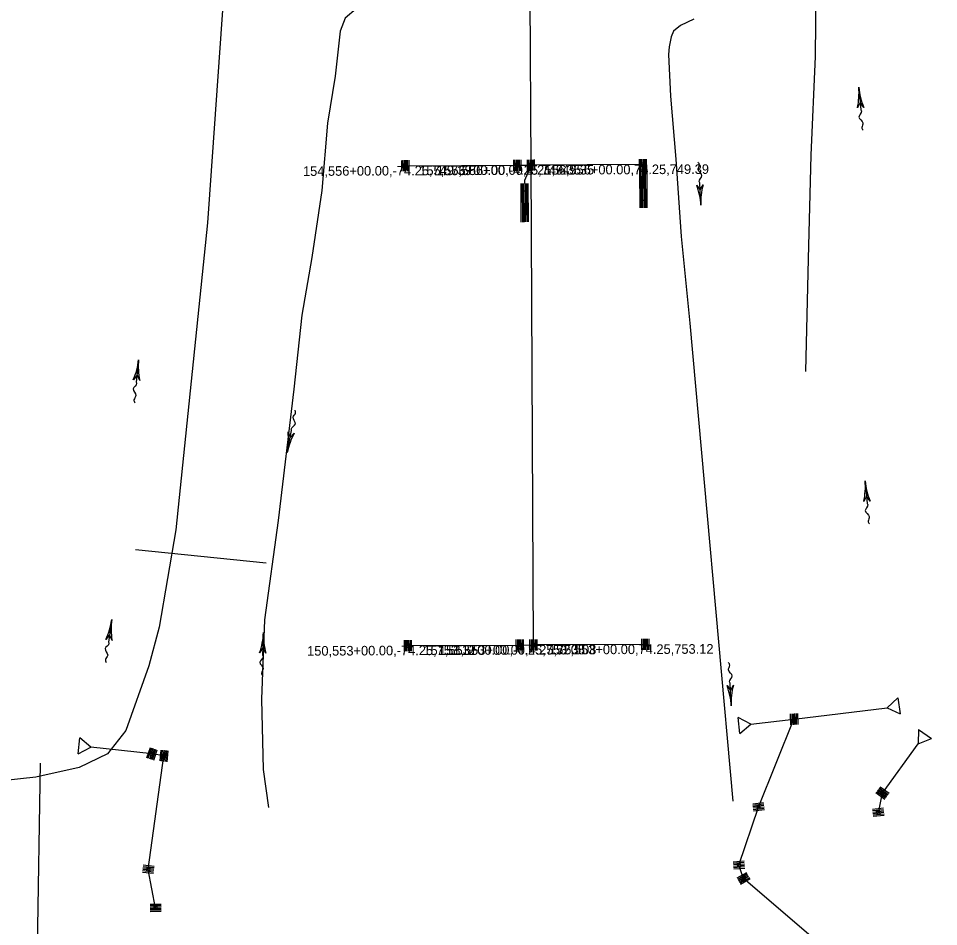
# Model space of a CAD drawing. Extents: x 593481 to 595602, y 151646 to 157396.
# Drawn here: x 594038 to 594613, y 154399 to 154967 of the extents above; entities that cross this region are included whole.
import ezdxf

# ---------------------------------------------------------------- set-up
doc = ezdxf.new("R2010")
doc.units = 0
for name, color, linetype in [('P_ALI_50_Equation', 7, 'Continuous'), ('P_DRN_Flow', 7, 'Continuous'), ('P_DRN_Inlet', 7, 'Continuous'), ('P_DRN_Pipes', 7, 'Continuous'), ('P_DRN_SS', 7, 'Continuous'), ('P_DRN_SS_UG', 7, 'Continuous')]:
    doc.layers.add(name, color=color, linetype=linetype)

msp = doc.modelspace()

# ---------------------------------------------------------------- linework, layer by layer
at = {"layer": 'P_DRN_Flow'}
for p, q in [((594563.04, 154923.95), (594564.3, 154909.88)), ((594464.36, 154850.16), (594463.66, 154864.27)), ((594112.88, 154753.62), (594111.44, 154739.56)), ((594205.82, 154695.54), (594208.51, 154709.41)), ((594567, 154677.84), (594568.26, 154663.77)), ((594096.09, 154591.1), (594094.11, 154577.11)), ((594190.93, 154582.97), (594190.43, 154568.85)), ((594483.33, 154537.28), (594482.62, 154551.39))]:
    msp.add_line(p, q, dxfattribs=at)
for points in [[(594566.18, 154911.38), (594563.9, 154914.39), (594562.19, 154911.02)], [(594461.72, 154862.84), (594463.88, 154859.75), (594465.72, 154863.05)], [(594113.56, 154740.68), (594111.9, 154744.07), (594109.59, 154741.09)], [(594206.29, 154708.49), (594207.64, 154704.96), (594210.22, 154707.73)], [(594570.14, 154665.27), (594567.86, 154668.28), (594566.15, 154664.91)], [(594096.28, 154578.15), (594094.75, 154581.6), (594092.32, 154578.71)], [(594192.48, 154570.11), (594190.59, 154573.38), (594188.48, 154570.25)], [(594480.69, 154549.96), (594482.84, 154546.86), (594484.68, 154550.16)]]:
    msp.add_lwpolyline(points, dxfattribs=at)
for centre, start, end in [((594521.25, 154920.21), 347.35833, 5.12065), ((594604.83, 154927.7), 185.12065, 202.88297), ((594422.46, 154848.06), 2.86546, 20.62778), ((594506.27, 154852.26), 165.10314, 182.86546), ((594071.14, 154757.91), 336.36566, 354.12798), ((594154.62, 154749.32), 174.12798, 191.8903), ((594164.63, 154703.54), 349.00666, 6.76898), ((594247, 154687.54), 151.24434, 169.00666), ((594525.21, 154674.09), 347.35833, 5.12065), ((594608.79, 154681.58), 185.12065, 202.88297), ((594054.55, 154597), 334.15876, 351.92108), ((594137.64, 154585.21), 171.92108, 189.6834), ((594149, 154584.46), 340.19919, 357.96151), ((594232.86, 154581.48), 177.96151, 195.72383), ((594441.42, 154535.18), 2.86546, 20.62778), ((594525.23, 154539.37), 165.10314, 182.86546)]:
    msp.add_arc(centre, 41.96, start, end, dxfattribs=at)
for points in [[(594564.3, 154909.88), (594564.68, 154909.13), (594563.13, 154905.36), (594565.67, 154901.65), (594564.98, 154898.75), (594565.76, 154897.09)], [(594463.66, 154864.27), (594463.3, 154865.04), (594465, 154868.74), (594462.61, 154872.55), (594463.41, 154875.42), (594462.7, 154877.11)], [(594111.44, 154739.56), (594111.67, 154738.75), (594109.43, 154735.35), (594111.21, 154731.22), (594109.98, 154728.51), (594110.43, 154726.72)], [(594208.51, 154709.41), (594208.35, 154710.24), (594210.89, 154713.43), (594209.48, 154717.7), (594210.95, 154720.29), (594210.66, 154722.11)], [(594568.26, 154663.77), (594568.64, 154663.01), (594567.09, 154659.25), (594569.63, 154655.54), (594568.94, 154652.64), (594569.72, 154650.97)], [(594094.11, 154577.11), (594094.31, 154576.29), (594091.94, 154572.98), (594093.56, 154568.79), (594092.23, 154566.12), (594092.61, 154564.33)], [(594190.43, 154568.85), (594190.71, 154568.05), (594188.7, 154564.51), (594190.76, 154560.51), (594189.72, 154557.72), (594190.28, 154555.97)], [(594482.62, 154551.39), (594482.27, 154552.15), (594483.97, 154555.86), (594481.58, 154559.66), (594482.38, 154562.53), (594481.66, 154564.23)]]:
    msp.add_spline(points, degree=3, dxfattribs=at)
at = {"layer": 'P_DRN_Inlet'}
for p, q in [((594277.49, 154871.4), (594277.45, 154878.27)), ((594278.39, 154871.4), (594278.35, 154878.28)), ((594279.29, 154871.41), (594279.25, 154878.28)), ((594280.19, 154871.41), (594280.15, 154878.29)), ((594281.09, 154871.42), (594281.05, 154878.29)), ((594281.99, 154871.42), (594281.95, 154878.3)), ((594347.49, 154871.76), (594347.45, 154878.63)), ((594348.39, 154871.76), (594348.35, 154878.64)), ((594349.29, 154871.77), (594349.25, 154878.64)), ((594350.19, 154871.77), (594350.15, 154878.65)), ((594351.09, 154871.78), (594351.05, 154878.65)), ((594351.99, 154871.78), (594351.95, 154878.66)), ((594355.99, 154871.8), (594355.95, 154878.68)), ((594356.89, 154871.81), (594356.85, 154878.68)), ((594357.79, 154871.81), (594357.75, 154878.69)), ((594358.69, 154871.81), (594358.65, 154878.69)), ((594359.59, 154871.82), (594359.55, 154878.69)), ((594360.49, 154871.82), (594360.45, 154878.7)), ((594425.99, 154872.16), (594425.95, 154879.04)), ((594426.89, 154872.16), (594426.85, 154879.04)), ((594427.79, 154872.17), (594427.75, 154879.04)), ((594428.69, 154872.17), (594428.65, 154879.05)), ((594429.59, 154872.18), (594429.55, 154879.05)), ((594430.49, 154872.18), (594430.45, 154879.06)), ((594425.99, 154872.6), (594426.11, 154848.6)), ((594426.89, 154872.6), (594427.01, 154848.6)), ((594427.79, 154872.61), (594427.91, 154848.61)), ((594428.69, 154872.61), (594428.81, 154848.61)), ((594429.59, 154872.62), (594429.71, 154848.62)), ((594430.49, 154872.62), (594430.61, 154848.62)), ((594351.77, 154863.71), (594351.89, 154839.71)), ((594352.67, 154863.72), (594352.79, 154839.72)), ((594353.57, 154863.72), (594353.69, 154839.72)), ((594354.47, 154863.73), (594354.59, 154839.73)), ((594355.37, 154863.73), (594355.49, 154839.73)), ((594356.27, 154863.74), (594356.39, 154839.74)), ((594279.03, 154571.4), (594278.99, 154578.28)), ((594279.93, 154571.41), (594279.89, 154578.28)), ((594280.83, 154571.41), (594280.79, 154578.29)), ((594281.73, 154571.42), (594281.69, 154578.29)), ((594282.63, 154571.42), (594282.59, 154578.3)), ((594283.53, 154571.43), (594283.49, 154578.3)), ((594349.03, 154571.76), (594348.99, 154578.64)), ((594349.93, 154571.77), (594349.89, 154578.64)), ((594350.83, 154571.77), (594350.79, 154578.65)), ((594351.73, 154571.78), (594351.69, 154578.65)), ((594352.63, 154571.78), (594352.59, 154578.65)), ((594353.53, 154571.78), (594353.49, 154578.66)), ((594357.53, 154571.8), (594357.49, 154578.68)), ((594358.43, 154571.81), (594358.39, 154578.68)), ((594359.33, 154571.81), (594359.29, 154578.69)), ((594360.23, 154571.82), (594360.19, 154578.69)), ((594361.13, 154571.82), (594361.09, 154578.7)), ((594362.03, 154571.83), (594361.99, 154578.7)), ((594427.53, 154572.16), (594427.49, 154579.04)), ((594428.43, 154572.17), (594428.39, 154579.04)), ((594429.33, 154572.17), (594429.29, 154579.05)), ((594430.23, 154572.18), (594430.19, 154579.05)), ((594431.13, 154572.18), (594431.09, 154579.06)), ((594432.03, 154572.19), (594431.99, 154579.06)), ((594520.24, 154532.25), (594520.38, 154525.38)), ((594521.14, 154532.27), (594521.28, 154525.4)), ((594522.04, 154532.29), (594522.18, 154525.42)), ((594522.94, 154532.31), (594523.08, 154525.44)), ((594523.84, 154532.33), (594523.98, 154525.45)), ((594524.74, 154532.35), (594524.88, 154525.47)), ((594118.1, 154504.73), (594120.32, 154511.24)), ((594118.95, 154504.44), (594121.17, 154510.94)), ((594119.8, 154504.15), (594122.03, 154510.65)), ((594120.65, 154503.86), (594122.88, 154510.36)), ((594121.5, 154503.57), (594123.73, 154510.07)), ((594122.35, 154503.27), (594124.58, 154509.78)), ((594126.76, 154509.59), (594126.05, 154502.75)), ((594127.65, 154509.49), (594126.95, 154502.66)), ((594128.55, 154509.4), (594127.84, 154502.56)), ((594129.44, 154509.31), (594128.74, 154502.47)), ((594130.34, 154509.22), (594129.63, 154502.38)), ((594131.23, 154509.12), (594130.53, 154502.29)), ((594579.3, 154478.71), (594573.76, 154482.79)), ((594579.83, 154479.44), (594574.3, 154483.51)), ((594580.37, 154480.16), (594574.83, 154484.24)), ((594580.9, 154480.89), (594575.36, 154484.96)), ((594581.43, 154481.61), (594575.89, 154485.69)), ((594581.97, 154482.34), (594576.43, 154486.41)), ((594503.56, 154476.57), (594496.73, 154475.8)), ((594503.66, 154475.68), (594496.83, 154474.91)), ((594503.76, 154474.79), (594496.93, 154474.02)), ((594503.86, 154473.89), (594497.03, 154473.12)), ((594503.96, 154473), (594497.13, 154472.23)), ((594504.06, 154472.1), (594497.23, 154471.33)), ((594578.47, 154473.14), (594571.64, 154472.4)), ((594578.57, 154472.24), (594571.73, 154471.5)), ((594578.67, 154471.35), (594571.83, 154470.61)), ((594578.76, 154470.45), (594571.93, 154469.71)), ((594578.86, 154469.56), (594572.02, 154468.82)), ((594578.96, 154468.66), (594572.12, 154467.92)), ((594122.51, 154435.95), (594115.67, 154436.64)), ((594122.6, 154436.85), (594115.76, 154437.53)), ((594491.43, 154440.07), (594484.57, 154439.54)), ((594491.5, 154439.17), (594484.64, 154438.64)), ((594491.56, 154438.27), (594484.71, 154437.74)), ((594491.63, 154437.38), (594484.78, 154436.85)), ((594491.7, 154436.48), (594484.85, 154435.95)), ((594122.15, 154432.37), (594115.31, 154433.06)), ((594122.24, 154433.27), (594115.4, 154433.95)), ((594122.33, 154434.16), (594115.49, 154434.85)), ((594122.42, 154435.06), (594115.58, 154435.74)), ((594491.77, 154435.58), (594484.92, 154435.05)), ((594492.84, 154432.84), (594486.91, 154429.37)), ((594493.3, 154432.07), (594487.36, 154428.59)), ((594493.75, 154431.29), (594487.82, 154427.82)), ((594494.21, 154430.51), (594488.27, 154427.04)), ((594494.66, 154429.74), (594488.73, 154426.26)), ((594495.11, 154428.96), (594489.18, 154425.49)), ((594126.93, 154413.03), (594120.06, 154413)), ((594126.94, 154412.13), (594120.06, 154412.1)), ((594126.94, 154411.23), (594120.07, 154411.2)), ((594126.95, 154410.33), (594120.07, 154410.3)), ((594126.95, 154409.43), (594120.08, 154409.4)), ((594126.96, 154408.53), (594120.08, 154408.5))]:
    msp.add_line(p, q, dxfattribs=at)
for points in [[(594280.73, 154873.85), (594280.72, 154875.85), (594278.72, 154875.84), (594278.73, 154873.84)], [(594350.73, 154874.21), (594350.72, 154876.21), (594348.72, 154876.2), (594348.73, 154874.2)], [(594359.23, 154874.26), (594359.22, 154876.26), (594357.22, 154876.24), (594357.23, 154874.24)], [(594429.23, 154874.61), (594429.22, 154876.61), (594427.22, 154876.6), (594427.23, 154874.6)], [(594427.26, 154867.88), (594427.34, 154853.33), (594429.34, 154853.34), (594429.26, 154867.89)], [(594353.04, 154858.99), (594353.12, 154844.45), (594355.12, 154844.46), (594355.04, 154859)], [(594282.27, 154573.86), (594282.26, 154575.86), (594280.26, 154575.85), (594280.27, 154573.85)], [(594352.27, 154574.22), (594352.26, 154576.22), (594350.26, 154576.21), (594350.27, 154574.21)], [(594360.77, 154574.26), (594360.76, 154576.26), (594358.76, 154576.25), (594358.77, 154574.25)], [(594430.77, 154574.62), (594430.76, 154576.62), (594428.76, 154576.61), (594428.77, 154574.61)], [(594521.54, 154529.84), (594521.58, 154527.84), (594523.58, 154527.88), (594523.54, 154529.88)], [(594121.96, 154505.98), (594122.61, 154507.88), (594120.72, 154508.52), (594120.07, 154506.63)], [(594127.75, 154507.03), (594127.54, 154505.04), (594129.53, 154504.84), (594129.74, 154506.83)], [(594579.26, 154482.78), (594577.65, 154483.96), (594576.47, 154482.35), (594578.08, 154481.16)], [(594501.28, 154475.06), (594499.29, 154474.84), (594499.51, 154472.85), (594501.5, 154473.07)], [(594576.18, 154471.63), (594574.19, 154471.42), (594574.41, 154469.43), (594576.4, 154469.64)], [(594489.09, 154438.63), (594487.1, 154438.48), (594487.25, 154436.49), (594489.25, 154436.64)], [(594120.05, 154435.85), (594118.06, 154436.05), (594117.86, 154434.06), (594119.85, 154433.86)], [(594491.37, 154430.53), (594489.64, 154429.52), (594490.65, 154427.8), (594492.38, 154428.81)], [(594124.5, 154411.77), (594122.5, 154411.76), (594122.51, 154409.76), (594124.51, 154409.77)]]:
    msp.add_lwpolyline(points, close=True, dxfattribs=at)
at = {"layer": 'P_DRN_Pipes'}
for p, q in [((594111.01, 154635.04), (594192.63, 154626.58)), ((594049.08, 154353.45), (594051.51, 154501.33))]:
    msp.add_line(p, q, dxfattribs=at)
at = {"layer": 'P_DRN_SS'}
for p, q in [((594587.38, 154542.13), (594580.72, 154536.05)), ((594587.38, 154542.13), (594588.89, 154532.25)), ((594580.72, 154536.05), (594588.89, 154532.25)), ((594495.64, 154525.68), (594487.64, 154529.84)), ((594488.73, 154519.9), (594487.64, 154529.84)), ((594488.73, 154519.9), (594495.64, 154525.68)), ((594075.06, 154507.18), (594076.16, 154517.12)), ((594083.06, 154511.32), (594076.16, 154517.12)), ((594600.31, 154522.45), (594600.26, 154513.43)), ((594600.31, 154522.45), (594608.6, 154516.86)), ((594075.06, 154507.18), (594083.06, 154511.32)), ((594600.26, 154513.43), (594608.6, 154516.86))]:
    msp.add_line(p, q, dxfattribs=at)
at = {"layer": 'P_DRN_SS_UG'}
for p, q in [((594358.22, 154875.25), (594356.68, 155175.25)), ((594279.72, 154874.85), (594349.72, 154875.21)), ((594349.72, 154875.21), (594358.22, 154875.25)), ((594428.22, 154875.61), (594358.22, 154875.25)), ((594359.76, 154575.25), (594358.22, 154875.25)), ((594428.22, 154875.61), (594428.24, 154872.61)), ((594281.26, 154574.85), (594351.26, 154575.21)), ((594351.26, 154575.21), (594359.76, 154575.25)), ((594429.76, 154575.61), (594359.76, 154575.25)), ((594522.56, 154528.86), (594580.72, 154536.05)), ((594495.64, 154525.68), (594522.56, 154528.86)), ((594500.4, 154473.95), (594522.56, 154528.86)), ((594121.34, 154507.25), (594083.06, 154511.26)), ((594577.86, 154482.56), (594600.26, 154513.43)), ((594118.96, 154434.88), (594128.64, 154505.94)), ((594128.64, 154505.94), (594121.34, 154507.25)), ((594575.3, 154470.53), (594577.86, 154482.56)), ((594491.01, 154429.16), (594488.17, 154437.56)), ((594123.51, 154410.76), (594118.96, 154434.88)), ((594540.34, 154386.88), (594491.01, 154429.16))]:
    msp.add_line(p, q, dxfattribs=at)
for points in [[(594195.87, 155406.63), (594155.86, 154839.17), (594136.12, 154647.32), (594125.75, 154586.3), (594119.28, 154562.31), (594104.8, 154521.76), (594093.35, 154507.25), (594075.71, 154498.55), (594048.65, 154492.71), (593981.57, 154485.26), (593546.85, 154493.19), (593538.17, 154494.28), (593526.38, 154497.62), (593514.24, 154502.72), (593501.23, 154504.79), (593491.32, 154504.17), (593484.5, 154500.86), (593481.17, 154494.41)], [(594612.95, 155388.89), (594596.71, 155382.2), (594588.1, 155375.16), (594577.39, 155362.81), (594571.35, 155352.38), (594563.26, 155330.97), (594554.94, 155301.9), (594548.34, 155267.44), (594543.77, 155237.13), (594542.73, 155208.88), (594537.26, 155024.38), (594536.51, 155006.73), (594535.72, 154943.23), (594533.09, 154881.6), (594531.45, 154816.64), (594529.67, 154746.17)], [(594248.94, 154972.9), (594241.91, 154967.19), (594238.79, 154958.94), (594235.75, 154930.84), (594230.88, 154901.44), (594227.52, 154859.43), (594221.1, 154817.5), (594214.83, 154781.45), (594209.84, 154735.27), (594200.1, 154653.01), (594191.65, 154590.92), (594189.63, 154541.3), (594190.82, 154497.49), (594193.99, 154473.57)], [(594459.87, 154966.54), (594451.71, 154962.63), (594447.21, 154958.98), (594445.84, 154955.46), (594444.61, 154949.3), (594444.11, 154944.45), (594445.4, 154918.3), (594448.79, 154879.03), (594451.96, 154830.72), (594457.48, 154776.54), (594484.29, 154477.7)], [(594358.22, 154875.25), (594354.02, 154865.72), (594354.03, 154863.72)], [(594488.17, 154437.56), (594500.4, 154473.95)]]:
    msp.add_lwpolyline(points, dxfattribs=at)

# ---------------------------------------------------------------- texts
at = {"layer": 'P_ALI_50_Equation'}
for s, p in [('154,556+00.00,-74.25,749.39', (594215.65, 154868.52)), ('155,556+00.00,-4.25,749.35', (594288.34, 154868.89)), ('157,556+00.00,4.25,749.35', (594299.3, 154868.95)), ('156,556+00.00,74.25,749.39', (594366.6, 154869.29)), ('150,553+00.00,-74.25,753.12', (594218.23, 154568.53)), ('151,553+00.00,-4.25,753.08', (594290.92, 154568.9)), ('153,553+00.00,4.25,753.08', (594300.65, 154568.95)), ('152,553+00.00,74.25,753.12', (594369.42, 154569.3))]:
    msp.add_text(s, height=6, rotation=0.29409, dxfattribs=at).set_placement(p)

doc.saveas('drawing.dxf')
